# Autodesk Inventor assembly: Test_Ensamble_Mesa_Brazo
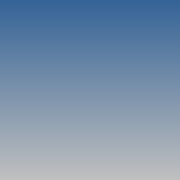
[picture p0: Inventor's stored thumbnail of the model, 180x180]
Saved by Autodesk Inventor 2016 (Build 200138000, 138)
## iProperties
Created: 2015-09
Part Number: Test_Ensamble_Mesa_Brazo
Document SubType Name: Assembly
Designer: julian.chica
Author: julian.chica
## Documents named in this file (1)
- C:\Test ExamProfessor 2015\Test_Ensamble_Mesa_Brazo.iam
